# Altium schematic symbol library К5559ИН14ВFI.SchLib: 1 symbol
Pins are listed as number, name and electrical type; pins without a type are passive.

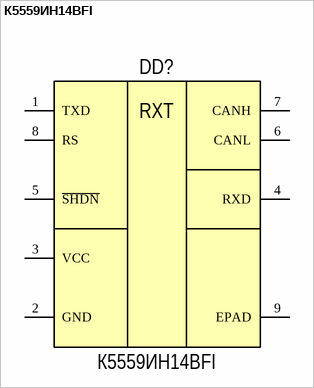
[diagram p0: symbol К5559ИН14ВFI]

## К5559ИН14ВFI
designator DD?  Part Number: К5559ИН14ВFI
FullName: Микросхема К5559ИН14ВFI ТСКЯ.431000.003ТУ, ТСКЯ.431323.049СП; Поставщик: Миландр
footprint К5559ИН14ВFI (DFN8 5x6x0,75 (1,27))
pins: 1 TXD, 2 GND, 3 VCC, 4 RXD, 5 ~{SHDN}, 6 CANL, 7 CANH, 8 RS, 9 EPAD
